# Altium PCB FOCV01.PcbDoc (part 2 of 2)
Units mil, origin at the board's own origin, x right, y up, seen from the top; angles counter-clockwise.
Board outline 3845.03 x 2425.03 mil, 2 copper layers (Top Layer, Bottom Layer); 118 components, 90 nets, 380 pads, 232 vias.
Unrouted connection lines stored in the file: 2.
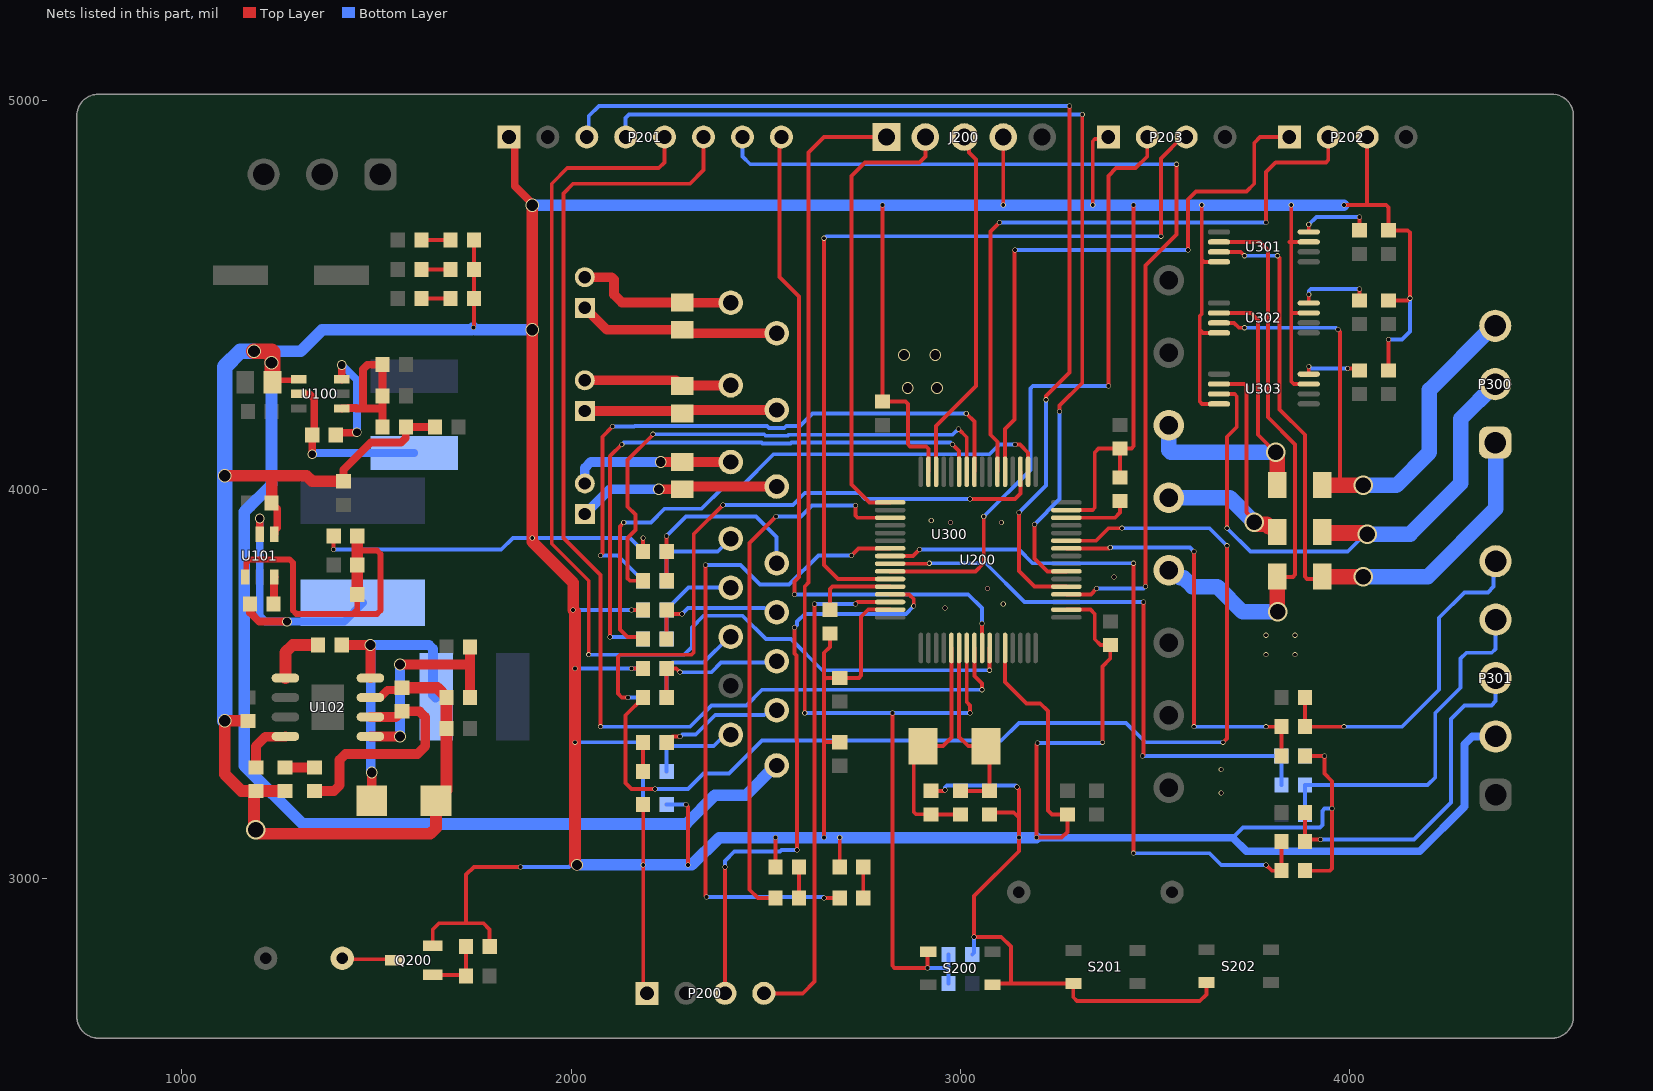
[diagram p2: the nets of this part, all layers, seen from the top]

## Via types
v1: diameter 13, hole 10, Top Layer to Bottom Layer, 174 vias
v2: diameter 30, hole 25, Top Layer to Bottom Layer, 15 vias
v3: diameter 25, hole 20, Top Layer to Bottom Layer, 12 vias
v4: diameter 35, hole 30, Top Layer to Bottom Layer, 11 vias
v5: diameter 24, hole 12, Top Layer to Bottom Layer, 8 vias
v6: diameter 50, hole 40, Top Layer to Bottom Layer, 7 vias
v7: diameter 45, hole 35, Top Layer to Bottom Layer, 4 vias
v8: diameter 20, hole 15, Top Layer to Bottom Layer, 1 vias

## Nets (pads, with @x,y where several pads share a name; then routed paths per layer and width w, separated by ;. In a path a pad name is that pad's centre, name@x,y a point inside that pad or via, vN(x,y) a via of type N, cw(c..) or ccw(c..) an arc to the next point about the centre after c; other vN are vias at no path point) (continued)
DGND: C103.1 C106.1 C107.1 C109.1 C110.2 C111.1 C112.1 C113.1 C200.1 C201.1 C202.1 C203.1 C204.2 C205.1 C206.1 C207.1 C208.1 C209.1 C306.1 C307.1 C308.1 C309.1 C310.1 C311.1 C312.1 C313.1 C314.1 C316.1 C317.1 C318.1 C319.1 C320.1 D100.1 D101.K D102.K D103.K J200.2 P200.1 P201.1 P202.3 P203.1 P301.2 Q200.2 R101.1 R102.2 R104.1 R108.1 R201.2 R205.2 R206.2 R207.2 R308.1 S200.1 S201.2 S202.2 U100.1 U101.1 U102.7 U200.12 U200.18 U200.31 U200.47 U200.63 U300.16 U301.4 U301.7 U302.4 U302.7 U303.4 U303.7 | length 25810.5
  Top Layer w10: v1(1389.68,3845.32) R104.1@1389.68,3880 ; Q200.2@1644.21,2827.4 1644.21,2869.21 1660,2885 1730,2885 ; v1(1748.81,4415.31) 1750.31,4416.81 D102.K@1750.31,4490 D103.K@1750.31,4565 D101.K@1750.32,4640 ; R205.2@1790.63,2825 1790.63,2869.37 1775,2885 1730,2885 ; v1(1870,3030) 1750,3030 1730,3010 1730,2885 ; v1(2155,3540) C311.1@2184.68,3540 ; v1(2155,3690) C309.1@2184.68,3690 ; C313.1@2184.69,3190 2185,3189.69 v1(2185,3035) 2185,2715 P200.1@2195,2705 ; C307.1@2184.68,3840 2184.68,3874.68 v1(2185,3875) ; v1(2295,3190) 2295,3189.19 2300,3184.19 v1(2300,3035) ; R207.2@2524.68,3029.69 2525,3030 v1(2525,3105) ; v1(2650,3105) 2650,3350.32 ; R201.2@2665,3629.68 2665,3595 2650,3580 2650,3509.46 ; C208.1@2680,3515.32 2655.86,3515.32 2650,3509.46 ; R206.2@2689.69,3029.69 2690,3030 v1(2690,3105) ; C207.1@2690,3350.32 2650,3350.32 ; C208.1@2690,3515.31 2739.14,3515.31 2745,3521.17 2745,3672.5 2763.18,3690.68 U200.63@2819.42,3690.68 ; v1(2800,4730) C209.1@2800,4225.31 2859.14,4225.31 2865,4219.46 2865,4115.86 2870.86,4110 2911.98,4110 2917.84,4104.14 U200.47@2917.84,4045 ; C200.1@2925,3225.31 2957.14,3225.31 2959.19,3227.36 v1(2960,3227.36) ; C201.1@3075,3164.68 3080.32,3170 3137.07,3170 3150,3157.07 ; S200.1@3082.68,2727.17 3085.51,2730 3129.14,2730 3129.5,2730.35 ; v1(3110,4730) J200.2@3110,4905 ; U200.12@3114.69,3592.25 3114.69,3505.31 3170,3450 3205,3450 3225,3430 3225,3175 3235.32,3164.68 C202.1@3275,3164.68 3275,3120 3260,3105 v1(3195,3105) 3195,3345 v1(3197.93,3347.93) ; v1(3145,3235) 3145,3234.19 3150,3229.19 3150,3157.07 ; U200.18@3272.16,3690.68 3334.32,3690.68 3345,3680 3345,3620 3345,3614.69 3359.69,3600 C206.1@3384.69,3600 ; U200.31@3272.16,3946.58 3339.14,3946.58 3345,3952.43 3345,4095 3354.68,4104.69 C205.1@3410,4104.69 ; v1(3340,4730) 3340,4894.14 3345.86,4900 3375,4900 P203.1@3380,4905 ; v1(3365,3350) 3365,3545 3385,3565 C206.1@3385,3599.69 ; C204.2@3410,4030.32 C205.1@3410,4104.69 ; v1(3445,4730) 3445,4110.54 3439.14,4104.69 C205.1@3410,4104.69 ; v1(3620,4730) 3620,4590 ; S202.2@3632.32,2732.68 3632.32,2702.32 3615,2685 3300,2685 3290,2695 S201.2@3290,2730.35 3129.5,2730.35 ; U303.4@3664.43,4219.26 3620.86,4219.26 3615,4225.11 3615,4410 ; U302.4@3664.43,4401.76 3623.24,4401.76 3615,4410 ; U301.4@3664.43,4584.26 3625.74,4584.26 3620,4590 ; 3845,4635.44 U301.7@3894.9,4635.44 ; 3850,4723.01 3850,4453.15 ; C320.1@3885.32,3020 3949.14,3020 3955,3025.86 3955,3250 3935,3270 v1(3935,3315) C312.1@3885.32,3315 ; U303.7@3894.9,4270.44 3856.33,4270.44 3850,4276.77 3850,4453.15 ; U302.7@3894.9,4452.94 3850.21,4452.94 3850,4453.15 ; v1(3985,4730) 4045,4730 ; P202.3@4045,4905 4045,4730 ; C318.1@4100,4305.31 v1(4100,4385) ; C317.1@4100,4485.31 4100.31,4485 4149.14,4485 v1(4155,4490.86) 4155,4659.46 4149.14,4665.31 C316.1@4100,4665.31 4100,4724.14 4094.14,4730 4045,4730 ; 2650,3350.32 2650,3509.46 ; 3129.5,2730.35 3129.5,2825.5 3105,2850 v1(3035,2850) 3035,2955 3150,3070 v1(3150,3105) 3150,3157.07 ; 3615,4410 3615,4445 3620,4450 3620,4590
  Top Layer w15: R102.2@1232.54,4275 1237.54,4280 1297.78,4280 U100.1@1300.17,4282.39
  Top Layer w20: C106.1@1230.31,3965 1230.31,3964.02 1245,3949.33 1245,3901.29 1237.39,3893.69 U101.1@1237.39,3884.83 ; C107.1@1415,4020.31 1415,4050 1485,4120 1563.28,4120 1575,4131.72 1575,4159.37 R101.1@1575.63,4160 C103.1@1650,4160 ; U102.7@1484.15,3465 1508.76,3465 1528.21,3484.46 1559.14,3484.46 C111.1@1565,3490.31 ; P201.1@1840,4905 1855,4890 1855,4779.06 1900,4734.06 v4(1900,4730)
  Top Layer w30: v4(1110,4035) 1230.31,4035 ; 1169.68,3225 1152.57,3225 1110,3267.57 v4(1110,3405) 1169.69,3405 C109.1@1170,3404.69 ; v6(1190,3125) v6@1189.64,3125 ; C106.1@1230.31,3965 1230.31,4035 ; C112.1@1265,3224.69 C113.1@1190,3224.69 1185,3219.69 1185,3129.64 v6@1189.64,3125 ; C107.1@1415,4020.31 1334.69,4020.31 1320,4035 1230.31,4035 ; C111.1@1565,3490.31 1649.69,3490.31 1650,3490 1655.67,3490 1679.68,3465.98 R108.1@1679.68,3465 C110.2@1679.69,3385 1679.69,3227.01 D100.1@1652.68,3200 1652.68,3129.64 1638.03,3115 1199.64,3115 v6@1189.64,3125 ; v4(1900,4730) v4(1900,4410) v1(1900,3875) 1900,3865 2005,3760 v1(2005,3690) 2010,3685 v1(2010,3540) v1(2010,3350) 2010,3040 v2(2015,3035)
  Top Layer w40: v4(1185,4355) 1230.09,4355 1232.54,4352.54 R102.2@1232.54,4275
  Bottom Layer w10: v1(1389.68,3845.32) 1820.32,3845.32 1850,3875 v1(1900,3875) 2150.67,3875 2184.69,3840.98 C306.1@2184.69,3840 2185,3840.31 v1(2185,3875) ; v1(1870,3030) 1994.59,3030 1999.59,3035 v2(2015,3035) ; v1(2005,3690) C308.1@2184.68,3690 ; v1(2010,3350) C314.1@2184.69,3350 ; v1(2010,3540) C310.1@2184.68,3540 ; R308.1@2245.31,3190 v1(2295,3190) ; v1(2960,3227.36) 2960.57,3227.93 2960.57,3234.14 2964.96,3238.53 3141.47,3238.53 v1(3145,3235) ; C203.1@3030.31,2805 3035,2809.68 v1(3035,2850) ; v1(3197.93,3347.93) 3362.12,3347.93 3364.19,3350 v1(3365,3350) ; 3700,3105 3726.31,3131.31 3924.14,3131.31 3930,3137.17 3930,3173.57 3935.86,3179.43 3954.43,3179.43 v1(3955,3180) ; C319.1@3885,3315 v1(3935,3315) ; v1(4100,4385) 4135,4385 4155,4405 v1(4155,4490.86)
  Bottom Layer w20: v1(3195,3105) 3700,3105 3735,3070 4180,3070 4295,3185 4295,3345 4315,3365 P301.2@4375,3365
  Bottom Layer w30: v4(1185,4355) 1305,4355 1360,4410 1743.5,4410 v1(1748.81,4415.31) ; v4(1230,4325) 1230,4012.15 1160,3942.15 1160,3290 1310,3140 2295,3140 2369,3214 2449,3214 2525.51,3290.51 U300.16@2527.76,3290.51 ; v1@1748.81,4415 1753.81,4410 v4(1900,4410) ; v4(1900,4730) v1(2800,4730) v1(3110,4730) v1(3445,4730) v1(3620,4730) v1(3850,4730) v1(3985,4730) ; v2(2015,3035) v1(2185,3035) v1(2300,3035) 2310,3035 2380,3105 v1(2525,3105) v1(2650,3105) v1(2690,3105) v1(3150,3105) v1(3195,3105)
  Bottom Layer w40: v4(1110,3405) v4(1110,4035) 1110,4315 1150,4355 v4(1185,4355)
  other v1: 3670,3220 3670,3280 3785,3575 3860,3575 3785,3625 3860,3625 2960,3695 3110,3705 3070,3745 3395,3775 2975,3915 3105,3915 2925,3920
  other v2: 2865,4260 2940,4260 2855,4345 2935,4345
FLASH_LED: D200.A U200.55 | length 1730.6
  Top Layer w10: v1(2345,3805) 2345,2955 v1(2347.5,2952.5) ; v1(2650,2950) 2689.37,2950 D200.A@2689.68,2949.69 ; v1(2720,3830) 2738.16,3848.16 U200.55@2819.42,3848.16
  Bottom Layer w10: v1(2345,3805) 2435,3805 2485,3755 2560,3755 2635,3830 v1(2720,3830) ; v1(2347.5,2952.5) 2647.5,2952.5 v1(2650,2950)
HSE_IN: C200.2 OSC200.1 R200.1 U200.5 | length 613.8
  Top Layer w10: U200.5@2976.89,3592.25 2976.89,3361.89 2955.01,3340.01 OSC200.1@2904.29,3340.01 2880,3315.72 2880,3170.86 2885.86,3165 2924.69,3165 C200.2@2925,3164.69 R200.1@3000,3164.69
HSE_OUT: C201.2 OSC200.2 R200.2 U200.6 | length 501.2
  Top Layer w10: U200.6@2996.58,3592.25 2996.58,3363.42 3020,3340 OSC200.2@3065.71,3340 3075,3330.71 C201.2@3075,3225.32 R200.2@3000,3225.32
I2C1_SCL: P200.3 U200.61 | length 1529.7
  Top Layer w10: P200.3@2395,2705 v1(2395,3030) ; v1(2573.5,3645) 2573.5,3578.24 2578.5,3573.24 2578.5,3357.5 2580,3356 v1(2580,3073.5) ; U200.61@2819.42,3730.05 2868.3,3730.05 2880,3718.35 v1(2880,3700)
  Bottom Layer w10: v1(2395,3030) 2395,3045 2419,3069 2536.22,3069 2540.72,3073.5 v1(2580,3073.5) ; v1(2573.5,3645) 2574.31,3645 2580.17,3650.86 2580.57,3650.86 2580.57,3660.57 2600,3680 2860,3680 v1(2880,3700)
I2C1_SDA: P200.4 U200.62 | length 1309.1
  Top Layer w10: P200.4@2495,2705 2595,2705 2625,2735 v1(2625,3705) ; v1(2730,3705) 2735.01,3710.01 2819.07,3710.01 U200.62@2819.42,3710.36
  Bottom Layer w10: v1(2625,3705) v1(2730,3705)
LCD_BLK: P201.8 U200.9 | length 1801.6
  Top Layer w10: P201.8@2540,4905 2535,4900 2535,4545 2585,4495 2585,3775 2573.5,3763.5 v1(2573.5,3730) ; v1(3055,3655) 3055.63,3654.37 U200.9@3055.63,3592.25
  Bottom Layer w10: v1(2573.5,3730) 3020,3730 3055,3695 v1(3055,3655)
LCD_DC: P201.6 U200.8 | length 3013.7
  Top Layer w10: v1(2075,3390) 2075,3780 1980,3875 1980,4760 2005,4785 2305,4785 2340,4820 P201.6@2340,4905 ; U200.8@3035.95,3592.25 3035.95,3520 3055,3500.95 v1(3055,3485)
  Bottom Layer w10: v1(2075,3390) 2305,3390 2360,3445 2450,3445 2490,3485 v1(3055,3485)
LCD_RES: P201.5 U200.10 | length 2843.4
  Top Layer w10: v1(2045,3575) 2045,3765 1950,3860 1950,4785 1990,4825 2225,4825 2240,4840 P201.5@2240,4905 ; v1(3075,3535) 3075.16,3535.16 3075.16,3592.09 U200.10@3075.32,3592.25
  Bottom Layer w10: v1@2044.85,3575 2290,3575 2310,3595 2310,3645 2340,3675 2440,3675 2500,3615 2565,3615 2645,3535 v1(3075,3535)
NetBuzzer200_2: Buzzer200.2 Q200.3 | length 136
  Top Layer w10: Buzzer200.2@1411.85,2795 1414.35,2792.5 1543.29,2792.5 Q200.3@1545.79,2790
NetC100_1: C100.1 U100.6 | length 284.3
  Top Layer w20: C100.1@1395.31,4140 1400.82,4145.5 1448.46,4145.5 v3(1449.42,4146.46) ; v3@1410,4320 v3(1410.41,4319.59) U100.6@1410.41,4282.4
  Bottom Layer w20: v3(1410.41,4319.59) 1450,4280 1450,4147.05 v3(1449.42,4146.46)
NetC100_2: C100.2 L100.1 U100.2 | length 448.2
  Top Layer w20: U100.2@1300.17,4245 1301,4244.17 1328.28,4244.17 1340,4232.45 C100.2@1340,4142.72 ; C100.2@1334.69,4140 1334.69,4090.31 v3(1335,4090)
  Bottom Layer w20: v3(1335,4090) 1336.35,4090 1339.66,4093.31 L100.1@1596.95,4093.31
NetC102_1: C102.1 R100.1 R101.2 U100.4 | length 423.1
  Top Layer w20: U100.4@1410.42,4207.6 1411.24,4208.43 1427.61,4208.43 1427.99,4208.8 1447.16,4208.8 1448.36,4207.6 1462.6,4207.6 ; R101.2@1515,4160 1515,4210 ; 1462.6,4207.6 1512.6,4207.6 1515,4210 ; 1462.6,4207.6 1465,4210 1465,4308.28 1476.72,4320 C102.1@1515,4320 R100.1@1515,4240 1515,4210
NetC104_1: C104.1 U101.6 | length 70.4
  Top Layer w20: C104.1@1235.31,3705 1236.57,3706.25 1236.57,3773.76 U101.6@1237.39,3774.59
NetC104_2: C104.2 L101.1 U101.2 | length 708.5
  Top Layer w20: C104.2@1174.68,3705 1174.68,3682.66 1175.99,3682.66 1198.65,3660 v3(1270,3660) ; U101.2@1200,3884.83 v3(1200,3925)
  Bottom Layer w20: v3(1200,3925) 1200,3675 1215,3660 v3(1270,3660) 1416.58,3660 L101.1@1465,3708.42
NetC105_1: C105.1 R103.1 R104.2 U101.4 | length 932.1
  Top Layer w15: U101.4@1162.6,3774.59 1165,3776.99 1165,3811.21 1173.79,3820 1276.21,3820 1285,3811.21 1285,3688.79 1293.79,3680 1440,3680 ; C105.1@1450.31,3730 1450.31,3690.31 1440,3680 ; 1450.32,3842.5 1501.21,3842.5 1510,3833.71 1510,3688.79 1501.21,3680 1440,3680
  Top Layer w30: C105.1@1450.31,3730 R103.1@1450.31,3805 1450.32,3842.5 R104.2@1450.32,3880
NetC108_1: C108.1 U102.1 | length 157.6
  Top Layer w30: U102.1@1265.85,3515 1265.85,3580.85 1285,3600 C108.1@1349.69,3600
NetC108_2: C108.2 D100.2 L102.1 U102.8 | length 852.8
  Top Layer w25: C108.2@1410.31,3600 v2(1484.15,3600) U102.8@1484.15,3515 ; D100.2@1487.32,3200 v2(1487.32,3272.32)
  Bottom Layer w25: v2(1487.32,3272.32) 1487.32,3273.68 1485,3276 1485,3599.15 v2(1484.15,3600) 1635,3600 1645,3590 1645,3471.35 L102.1@1651.35,3465
NetC111_2: C111.2 R107.2 U102.6 | length 600.5
  Top Layer w25: R107.2@1340,3224.68 1390.36,3224.68 1405,3239.33 1405,3305 1420,3320 1605.36,3320 1625,3339.64 1625,3415.04 1610.36,3429.69 C111.2@1565,3429.69 1564.02,3429.69 1549.33,3415 U102.6@1484.15,3415 U102.6@1484.84,3414.31
NetC112_2: C112.2 R107.1 | length 75
  Top Layer w25: C112.2@1265,3285.31 R107.1@1340,3285.31
NetC113_2: C113.2 U102.4 | length 140.9
  Top Layer w25: C113.2@1190,3285.31 1190,3340 1214.31,3364.31 1265.16,3364.31 U102.4@1265.85,3365
NetC204_1: C204.1 U200.30 | length 172.9
  Top Layer w10: U200.30@3272.16,3926.9 3367.21,3926.9 3396.9,3926.9 3410,3940 C204.1@3410,3969.68
NetC300_1: C300.1 C301.1 U300.2 | length 525.1
  Top Layer w25: C300.1@2035,4466.26 2091.3,4409.96 C301.1@2285,4409.96 2294.22,4400.74 U300.2@2527.76,4400.74
  Bottom Layer w10: U300.2@2524.07,4404.43 U300.2@2527.76,4400.74
NetC300_2: C300.2 C301.2 U300.1 | length 424.7
  Top Layer w25: C300.2@2035,4545 2104.14,4545 2110,4539.14 2110,4500 2129.96,4480.04 C301.2@2285,4480.04 2285.55,4479.49 U300.1@2409.65,4479.49
NetC302_1: C302.1 C304.1 U300.4 | length 499.1
  Top Layer w25: C302.1@2035,4201.26 2278.7,4201.26 C304.1@2285,4194.96 2293.93,4203.9 U300.4@2527.76,4203.9
NetC302_2: C302.2 C304.2 U300.3 | length 381.6
  Top Layer w25: C302.2@2035,4280 2270.04,4280 C304.2@2285,4265.04 2286.85,4266.89 U300.3@2409.65,4266.89
NetC303_1: C303.1 C305.1 U300.6 | length 522.1
  Top Layer w25: v2(2225,4000) v2(2225,4000) C305.1@2285,3999.96 2292.08,4007.04 U300.6@2527.76,4007.04
  Bottom Layer w25: C303.1@2035,3936.26 2098.74,4000 v2(2225,4000)
NetC303_2: C303.2 C305.2 U300.5 | length 420.9
  Top Layer w25: v2(2230,4070) C305.2@2285,4070.04 C305.2@2285,4070.04 U300.5@2409.65,4070.03
  Bottom Layer w25: C303.2@2035,4015 2035,4055 2050,4070 v2(2230,4070)
NetC306_2: C306.2 R300.2 U300.7 | length 253.1
  Bottom Layer w10: R300.2@2245.32,3765 C306.2@2245.31,3840 2376.46,3840 U300.7@2409.65,3873.18
NetC307_2: C307.2 R301.2 U300.8 | length 507.8
  Top Layer w10: v1(2245,3880) 2245.31,3879.69 C307.2@2245.31,3840 R301.2@2245.32,3765 ; U300.8@2527.56,3810 U300.8@2527.76,3810.19
  Bottom Layer w10: v1(2245,3880) 2295,3930 2475,3930 2527.76,3877.24 U300.8@2527.76,3810.19
NetC308_2: C308.2 R302.2 U300.9 | length 263.6
  Bottom Layer w10: R302.2@2245.32,3615 C308.2@2245.32,3690 2245.32,3690.98 2301.53,3747.2 U300.9@2409.65,3747.2
NetC309_2: C309.2 R303.2 U300.10 | length 372.4
  Top Layer w10: R303.2@2245,3615 2245,3689.69 C309.2@2245.32,3690 2255.32,3680 v1(2285,3680)
  Bottom Layer w10: v1(2285,3680) 2300,3695 2495.4,3695 2496.05,3694.35 2517.62,3694.35 U300.10@2527.76,3684.21
NetC310_2: C310.2 R304.2 U300.11 | length 275.2
  Bottom Layer w10: R304.2@2245.32,3465 C310.2@2245.32,3540.98 ; C310.2@2245.32,3540 C310.2@2245.32,3540.98 ; U300.11@2409.65,3620.5 U300.11@2409.65,3621.22 2406.22,3621.22 2340,3555 2260.32,3555 2259.61,3554.29 2258.62,3554.29 C310.2@2245.32,3540.98
NetC311_2: C311.2 R305.2 U300.12 | length 377.8
  Top Layer w10: R305.2@2245.32,3465 C311.2@2245.32,3540 2270,3540 v1(2280,3530) ; U300.12@2524.53,3555 U300.12@2527.76,3558.22
  Bottom Layer w10: v1(2280,3530) 2360,3530 2385,3555 2524.53,3555 U300.12@2527.76,3558.22
NetC314_2: C314.2 R307.2 U300.15 | length 256.6
  Bottom Layer w10: R307.2@2245.32,3275 C314.2@2245.32,3350.98 ; C314.2@2245.32,3350 2255.32,3340 2366.31,3340 2395.55,3369.25 U300.15@2409.65,3369.25
NetD101_A: D101.A R111.1 | length 74.4
  Top Layer w10: R111.1@1615.31,4640 D101.A@1689.68,4640
NetD102_A: D102.A R112.1 | length 74.4
  Top Layer w10: R112.1@1615.31,4490 D102.A@1689.68,4490
NetD103_A: D103.A R110.1 | length 75.4
  Top Layer w10: R110.1@1615.31,4565 1687.18,4565 D103.A@1689.68,4562.5
NetD200_K: D200.K R206.1 | length 80
  Top Layer w10: D200.K@2750.31,2949.69 R206.1@2750.32,3029.68
NetD201_K: D201.K R207.1 | length 80
  Top Layer w10: D201.K@2585.31,2949.69 R207.1@2585.31,3029.69
NetD300_K: D300.K R306.2 | length 75.8
  Top Layer w10: D300.K@2184.69,3275 2184.69,3348.18 R306.2@2186.5,3350
NetP301_3: P301.3 R315.1 R318.2 | length 899.2
  Top Layer w10: R318.2@3885.32,3170 R315.1@3885.31,3095 3890.31,3100 v1(3925,3100)
  Bottom Layer w10: v1(3925,3100) 4165,3100 4260,3195 4260,3410 4295,3445 4364.14,3445 4375,3455.86 P301.3@4375,3515
NetP301_4: P301.4 R316.1 R319.2 | length 925.2
  Bottom Layer w10: R319.2@3885.32,3165 R316.1@3885.32,3240 4200,3240 4220,3260 4220,3425 4285,3490 4285,3565 4300,3580 4365,3580 4375,3590 P301.4@4375,3665
NetP301_5: P301.5 R317.1 R320.2 | length 884.2
  Top Layer w10: R320.2@3885.32,3465 R317.1@3885.31,3390 v1(3985,3390)
  Bottom Layer w10: v1(3985,3390) 4135,3390 4230,3485 4230,3670 4295,3735 4355,3735 4370,3750 4370,3810 P301.5@4375,3815
NetQ200_1: Q200.1 R204.2 R205.1 | length 161.7
  Top Layer w10: Q200.1@1644.21,2752.6 1727.09,2752.6 R204.2@1729.68,2750 1729.68,2824.68 R205.1@1730,2825
NetR106_1: R106.1 R108.2 U102.5 | length 571.2
  Top Layer w25: U102.5@1484.15,3365 v2(1560,3365) ; v2(1560,3550) 1740.32,3550 ; R108.2@1740.32,3465 1740.32,3550 ; R106.1@1740.31,3595 1740.32,3550
  Bottom Layer w25: v2(1560,3365) v2(1560,3550)
NetR201_1: R201.1 U200.60 | length 209.6
  Top Layer w10: R201.1@2665,3691.13 2665,3743.87 2670.86,3749.73 U200.60@2819.42,3749.73
NetR306_1: R306.1 U300.14 | length 316.5
  Top Layer w10: R306.1@2245.31,3350 2260.31,3365 v1(2280,3365)
  Bottom Layer w10: v1(2280,3365) 2280.81,3365 2285.81,3370 2320,3370 2370,3420 2495.4,3420 2497.5,3422.1 2517.62,3422.1 U300.14@2527.76,3432.24
NetR307_1: R307.1 R308.2 | length 85
  Bottom Layer w10: R308.2@2184.68,3190 2184.68,3225 R307.1@2184.69,3275
NetR312_1: R312.1 U301.8 | length 198.2
  Top Layer w10: U301.8@3894.9,4661.03 v1(3894.9,4679.9) v1@3895,4680 ; R312.1@4020.71,4661.03 R312.1@4025,4665.31 v1(4025,4700)
  Bottom Layer w10: v1(3894.9,4679.9) 3915,4700 v1(4025,4700)
NetR313_1: R313.1 U302.8 | length 202.4
  Top Layer w10: U302.8@3894.9,4478.53 3894.9,4499.9 v1(3895,4500) ; R313.1@4018.21,4478.53 R313.1@4025,4485.31 v1(4025,4515)
  Bottom Layer w10: v1(3895,4500) 3895,4509.14 3900.86,4515 v1(4025,4515)
NetR314_1: R314.1 U303.8 | length 157.2
  Top Layer w10: U303.8@3894.9,4296.03 3894.9,4314.9 v1(3895,4315) ; v1(3995,4310) 4010.31,4310 4015.31,4315 R314.1@4025,4305.31
  Bottom Layer w10: v1(3895,4315) 3900,4310 v1(3995,4310)
NRST: C203.2 J200.5 R203.1 S200.4 U200.7 | length 3210.6
  Top Layer w10: v1(2600,3425) 2600,3750 2610,3760 2610,4865 2650,4905 J200.5@2810,4905 ; v1(2825,3425) 2825,2775.86 2830.86,2770 v1(2915,2770) 2915,2809.5 S200.4@2917.32,2811.82 ; U200.7@3016.26,3592.25 3016.26,3453.74 3025,3445 v1(3025,3425)
  Bottom Layer w10: v1(2600,3425) v1(2825,3425) v1(3025,3425) ; v1(2915,2770) 2969.69,2770 ; R203.1@2969.69,2730 2969.69,2765.05 ; 2969.69,2765.05 C203.2@2969.69,2805 2969.69,2765.05
SPI1_MOSI: P201.4 U200.23 | length 2513.5
  Top Layer w10: v1(3190,3910) 3190,3822.37 3223.28,3789.1 U200.23@3272.16,3789.1 ; v1(3255,4200) 3255,4215 3313.12,4273.12 v1(3313.12,4963.12)
  Bottom Layer w10: P201.4@2140,4905 2140,4953.83 2148.67,4962.5 3312.5,4962.5 v1(3313.12,4963.12) ; v1(3190,3910) 3255,3975 v1(3255,4200)
SPI1_NSS: P201.7 U200.20 | length 2502.5
  Top Layer w10: U200.20@3272.16,3730.05 3335.05,3730.05 v1(3350,3745) ; v1(3475,3750) 3475,4575 3555,4655 v1(3555,4835)
  Bottom Layer w10: P201.7@2440,4905 2440,4855 2460,4835 v1(3555,4835) ; v1(3350,3745) 3470,3745 v1(3475,3750)
SPI1_SCK: P201.3 U200.21 | length 2689.4
  Top Layer w10: v1(3150,3940) 3150,3790 3190.27,3749.73 U200.21@3272.16,3749.73 ; v1(3220,4230) 3220,4240 3280,4300 v1(3280,4985)
  Bottom Layer w10: P201.3@2040,4905 2045,4910 2045,4958.83 2071.17,4985 v1(3280,4985) ; v1(3150,3940) 3220,4010 v1(3220,4230)
SWCLK: J200.4 U200.49 | length 1172
  Top Layer w10: U200.49@2819.42,3966.27 2765.86,3966.27 2760,3972.12 2720,4012.12 2720,4805 2755,4840 2895,4840 2910,4855 J200.4@2910,4905
SWDIO: J200.3 U200.46 | length 909.3
  Top Layer w10: U200.46@2937.52,4045 2937.52,4162.52 3040,4265 3040,4846.88 3021.6,4865.28 3021.6,4876.88 3010.45,4888.04 J200.3@2998.84,4888.04
TIM1_CH1: R300.1 U200.41 | length 1566.9
  Top Layer w10: v1(2075,3830) 2075,3830.81 2080,3835.81 2080,4135 v1(2106.25,4161.25) ; v1(3015,4195) 3035.95,4174.05 U200.41@3035.95,4045
  Bottom Layer w10: v1(2075,3830) 2119.68,3830 R300.1@2184.68,3765 ; v1(2106.25,4161.25) 2162.11,4161.25 2163.86,4163 2502.9,4163 2508.5,4157.4 2547.02,4157.4 2552.62,4163 2588,4163 2620,4195 v1(3015,4195)
TIM1_CH1N: R303.1 U200.34 | length 1528.1
  Top Layer w10: v1(2135,3915) 2135,3914.19 2125,3904.19 2125,3640 2145,3620 2179.37,3620 R303.1@2184.37,3615 ; v1(3140,4115) 3152.63,4115 3173.74,4093.89 U200.34@3173.74,4045
  Bottom Layer w10: v1(2135,3915) 2205,3915 2240,3950 2335,3950 2390,4005 2435,4005 2520,4090 3075,4090 3100,4115 v1(3140,4115)
TIM1_CH2: R301.1 U200.42 | length 1369
  Top Layer w10: R301.1@2184.68,3765 2150.86,3765 2145,3770.86 2145,3875 2165,3895 2165,3935 2145,3955 2145,4075 2210,4140 v1(2210,4141.5) ; v1(2995,4155) 3016.26,4133.74 U200.42@3016.26,4045
  Bottom Layer w10: v1(2210,4141.5) 2496.11,4141.5 2500.21,4137.4 2555.3,4137.4 2557.9,4140 2979.59,4140 2994.59,4155 v1(2995,4155)
TIM1_CH2N: R304.1 U200.35 | length 1617.5
  Top Layer w10: v1(2145.81,3465) 2130,3465 2120,3475 2120,3569.14 2125.86,3575 2309.14,3575 2315,3580.86 2315,3885 v1(2390,3960) ; v1(3025,3975) 3140,3975 3154.06,3989.06 U200.35@3154.06,4045
  Bottom Layer w10: v1(2145.81,3465) R304.1@2184.69,3465 ; v1(2390,3960) 2570,3960 2600,3990 2740,3990 2755,3975 v1(3025,3975)
TIM1_CH3: R302.1 U200.43 | length 1527.3
  Top Layer w10: v1(2100,3620) 2100,4085 v1(2130,4115) ; v1(2980,4115) 2996.58,4098.42 U200.43@2996.58,4045
  Bottom Layer w10: v1(2100,3620) 2179.69,3620 R302.1@2184.69,3615 ; v1(2130,4115) 2130.81,4115 2135.81,4120 2489.33,4120 2491.93,4117.4 2563.58,4117.4 2566.18,4120 2974.19,4120 2979.19,4115 v1(2980,4115)
TIM1_CH3N: R305.1 U200.27 | length 2824.8
  Top Layer w10: R305.1@2184.69,3465 2184.69,3464.02 2140,3419.33 2140,3245 2155,3230 v1(2215,3230) ; U200.27@3272.16,3867.84 3347.84,3867.84 3380,3900 v1(3415,3900) ; v1(3675,3350) 3685,3360 v1(3685,3855)
  Bottom Layer w10: v1(2215,3230) 2300,3230 2340,3270 2405,3270 2490,3355 3105,3355 3150,3400 3425,3400 3475,3350 v1(3675,3350) ; v1(3415,3900) 3640,3900 v1(3685,3855)
TIM3_CH1: C320.2 R315.2 U200.56 | length 2073.5
  Top Layer w10: U200.56@2819.42,3828.47 2878.47,3828.47 v1(2895,3845) ; v1(3445,3065) v1(3445,3810) 3445,3601.78 ; v1(3785,3035) 3800,3020 C320.2@3824.68,3020 R315.2@3824.68,3095
  Bottom Layer w10: v1(2895,3845) 3150.31,3845 3185.31,3810 v1(3445,3810) ; v1(3445,3065) 3640,3065 3670,3035 v1(3785,3035)
TIM3_CH2: C319.2 R316.2 U200.57 | length 1520.1
  Top Layer w10: U200.57@2819.42,3808.79 2917.97,3808.79 2919.19,3810 v1(2920,3810) ; v1(3467.5,3315) 3470,3317.5 v1(3470,3710)
  Bottom Layer w10: v1(2920,3810) 3065,3810 3165,3710 v1(3470,3710) ; v1(3467.5,3315) C319.2@3824.37,3315 ; R316.2@3824.69,3240 C319.2@3824.69,3314.69
TIM3_CH3: C312.2 R317.2 U200.26 | length 1081.4
  Top Layer w10: U200.26@3272.16,3848.16 3382.34,3848.16 3384.19,3850 v1(3385,3850) ; v1(3600,3390) v1(3600,3840) ; v1(3785,3390) R317.2@3824.68,3390 ; C312.2@3824.68,3315 R317.2@3824.68,3389.02
  Bottom Layer w10: v1(3385,3850) 3590,3850 v1(3600,3840) ; v1(3600,3390) v1(3785,3390)
U: P300.3 R309.2 U302.3 | length 1431.7
  Top Layer w10: U302.3@3664.43,4427.35 3703,4427.35 3715.35,4415 v1(3730,4415) ; v1(3970,4410) 3970,4409.19 3975,4404.19 3975,4010.48 3975,4010
  Top Layer w40: R309.2@3930.22,4020.2 R309.2@3930.22,4010.48 3975,4010.48 v6@4034.82,4010.48
  Bottom Layer w10: v1(3730,4415) 3965,4415 v1(3970,4410)
  Bottom Layer w40: v6(4035,4010) 4120,4010 4205,4095 4205,4255 4370,4420 P300.3@4374.02,4420
U_IN: R309.1 U300.22 U302.2 | length 893.9
  Top Layer w10: U302.2@3664.43,4452.94 3747.06,4452.94 3765,4435 3765,4140 v6(3810,4095)
  Top Layer w40: v6(3810,4095) 3810,4092.29 3813.78,4088.51 R309.1@3813.78,4010.48
  Bottom Layer w40: U300.22@3535.63,4164.33 3535,4163.7 3535,4100.86 3540.86,4095 v6(3810,4095)
USART1_RX: P203.3 U200.59 | length 2179
  Top Layer w10: v1(2650,4645) 2650,3805 2685.58,3769.42 U200.59@2819.42,3769.42 ; v1(3515,4650) 3515,4850 3570,4905 P203.3@3580,4905
  Bottom Layer w10: v1(2650,4645) 2650.81,4645 2655.81,4650 v1(3515,4650)
USART1_TX: P203.2 U200.58 | length 1661.2
  Top Layer w10: U200.58@2819.42,3789.1 3039.1,3789.1 3060,3810 v1(3060,3930) ; v1(3380,4265) 3380,4805 3400,4825 3450,4825 3480,4855 P203.2@3480,4905
  Bottom Layer w10: v1(3060,3930) 3180,4050 3180,4259.14 3185.86,4265 v1(3380,4265)
USART6_RX: P202.2 U200.38 | length 1703.8
  Top Layer w10: U200.38@3095,4045 3095,4122.07 3077.07,4140 3077.07,4662.07 v1(3100,4685) ; v1(3785,4685) 3785,4815 3810,4840 3939.14,4840 3945,4845.86 P202.2@3945,4905
  Bottom Layer w10: v1(3100,4685) v1(3785,4685)
USART6_TX: P202.1 U200.37 | length 1543.3
  Top Layer w10: U200.37@3114.69,4045 3114.69,4154.69 3139.17,4179.17 3139.17,4614.17 v1(3140,4615) ; v1(3585,4615) 3585,4745 3605,4765 3735,4765 3755,4785 3755,4890 3770,4905 P202.1@3845,4905
  Bottom Layer w10: v1(3140,4615) v1(3585,4615)
USER_LED: D201.A U200.51 | length 1395.1
  Top Layer w10: D201.A@2524.68,2949.69 2524.37,2950 2479.7,2950 2458.5,2971.2 2458.5,3862.31 v1(2526.19,3930) ; v1(2730,3958.49) 2730,3932.75 2735.86,3926.9 U200.51@2819.42,3926.9
  Bottom Layer w10: v1(2526.19,3930) 2590,3930 2618.49,3958.49 v1(2730,3958.49)
V: P300.2 R310.2 U303.3 | length 1499.9
  Top Layer w10: U303.3@3664.43,4244.85 3664.58,4245 3704.14,4245 3710,4239.14 3710,4160 3685,4135 v1(3685,3900)
  Top Layer w40: R310.2@3930.22,3890.48 3932.97,3887.74 v6@4042.26,3887.74
  Bottom Layer w10: v1(3685,3900) 3745,3840 3995,3840 4040,3885 v6(4045,3885)
  Bottom Layer w40: v6(4045,3885) 4155,3885 4285,4015 4285,4180.98 P300.2@4374.02,4270
V_IN: R310.1 U300.21 U303.2 | length 751
  Top Layer w10: U303.2@3664.43,4270.44 3729.14,4270.44 3735,4264.58 3735,3940.86 3755,3920.86 v6(3755,3915)
  Top Layer w40: v6(3755,3915) 3757.71,3915 3762.71,3910 3786.58,3910 3792.61,3903.97 3810.01,3903.97 3813.78,3900.2 R310.1@3813.78,3890.48
  Bottom Layer w40: U300.21@3535.63,3978.11 3691.89,3978.11 v6(3755,3915)
W: P300.1 R311.2 U301.3 | length 1740.2
  Top Layer w10: U301.3@3664.43,4609.85 3720.15,4609.85 v1(3730,4600) ; v1(3815,4600) 3815,4599.19 3820,4594.19 3820,4205 3885,4140 3885,3775.86 3890.86,3770 3924.74,3770 R311.2@3930.22,3775.48
  Top Layer w40: R311.2@3930.22,3775.48 3930.71,3775 v6@4029.59,3775
  Bottom Layer w10: v1(3730,4600) v1(3815,4600)
  Bottom Layer w40: v6(4035,3775) 4200,3775 4375,3950 4375,4119.02 P300.1@4374.02,4120
W_IN: R311.1 U300.20 U301.2 | length 1459.1
  Top Layer w10: U301.2@3664.43,4635.44 3769.56,4635.44 3790,4615 3790,4185 3860,4115 3860,3780.73 3854.14,3774.88 R311.1@3814.39,3774.88
  Top Layer w40: R311.1@3814.39,3774.88 3814.39,3685.61 v6(3815,3685)
  Bottom Layer w40: U300.20@3535.63,3791.89 3546.11,3791.89 3565.48,3772.52 3573.34,3772.52 3595.86,3750 3660,3750 3725,3685 v6(3815,3685)
pads on no net: P100.3 S200.2 S200.3 S201.1 S201.3 S202.1 S202.3 U100.5 U101.5 U102.3 U102.9 U200.2 U200.3 U200.4 U200.11 U200.17 U200.22 U200.24 U200.25 U200.28 U200.29 U200.33 U200.36 U200.39 U200.40 U200.44 U200.45 U200.50 U300.24 U301.1 U302.1 U303.1
copper on no net:
  other v5: 1355.31,3420.31 1355.31,3420.31 1394.68,3420.31 1394.68,3420.31 1355.31,3459.68 1355.31,3459.68 1394.68,3459.68 1394.68,3459.68

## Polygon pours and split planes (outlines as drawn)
DGND on Top Layer "NONET_L02_P-001" (solid, remove dead copper, pour order 0): 2625,2985 3940,2985 3940,4370 2625,4370
DGND on Bottom Layer "NONET_L02_P-001" (solid, remove dead copper, pour order 1): 2625,4380 2625,2985 3940,2985 3940,4380

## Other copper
Top Layer:
  rectangle net 3V3DD: 3865,4210 3925,4250
  rectangle net 3V3DD: 3865,4575 3925,4615
  rectangle net 3V3DD: 3865,4395 3925,4435
  pour cut-out: 3115,3415 3115,3265 3110,3270 2855,3270 2855,3410 2850,3415
Bottom Layer:
  pour cut-out: 2845,3440 2850,3435 3125,3435 3125,3260 3120,3265 2845,3265

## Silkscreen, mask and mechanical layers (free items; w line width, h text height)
Top Overlay:
  circle w10: c865,4880 r108.27
  circle w10: c865,2725 r108.27
  circle w10: c4445,2725 r108.27
  circle w10: c4445,4880 r108.27
  text "A5" at 2009.96,4960.64 h60
  text "C2" at 2210,4960.64 h60
  text "C0" at 2310,4960.64 h60
  text "C1" at 2510,4960.64 h60
  text "A7" at 2109.96,4960 h60
  text "A4" at 2409.96,4960 h60
  text "24V" at 990,4920 h60 r270
  text "DG" at 4010,4810.64 h60
  text "3V3" at 4110,4810.64 h60
  text "TX" at 3805,4810 h60
  text "RX" at 3905,4810 h60
  text "DG" at 1805,4805.64 h60
  text "SCK" at 2000,4805.64 h60
  text "RES" at 2195,4805.64 h60
  text "NSS" at 2389,4805.64 h60
  text "DG" at 3350,4805.64 h60
  text "3V3" at 3635,4805.64 h60
  text "TX" at 3445,4805 h60
  text "RX" at 3540,4805 h60
  text "调试打印口" at 3415,4760.44 h60
  text "通讯UART6" at 3870.04,4758.38 h60
  text "3V3" at 1895,4755.64 h60
  text "MOSI" at 2091,4755.64 h60
  text "DC" at 2310,4755.64 h60
  text "BLK" at 2495,4755 h60
  text "_" at 1345,4740.69 h60
  text "DG" at 3080,4720.64 h60
  text "3V3" at 3180,4720.64 h60
  text "下载口" at 2840.04,4720.25 h60
  text "+" at 1485,4713.77 h60
  text "LCD" at 2215,4685.64 h60
  text "15V" at 1800,4630.64 h60
  text "W_IN" at 3500,4630.61 h60
  text "电机接口" at 4330.04,4595.66 h60
  text "5V" at 1810,4550.64 h60
  text "3V" at 1810,4480.64 h60
  text "U_IN" at 3510.4,4428.94 h60
  text "U->" at 4220.6,4395.64 h60
  text "磁珠" at 1070.03,4263.5 h40
  text "V->" at 4219.7,4255 h60
  text "V_IN" at 3509.8,4248.94 h60
  text "W->" at 4205,4105 h60
  text "霍尔传感器接口" at 4250.66,3874.96 h60 r270
  text "HU->" at 4110,3790.64 h60
  text "HV->" at 4110,3650 h60
  text "HW->" at 4110,3500 h60
  text "DG" at 4260.64,3405 h60 r270
  text "CH3" at 3605,3370.64 h60
  text "5VDD" at 4260.64,3285 h60 r270
  text "故障指示" at 2285.04,3255.36 h60
  text "CH2" at 3605,3220.64 h60
  text "CH1" at 3605,3070.64 h60
  text "DG" at 1170,3070.43 h40
  text "USER" at 2490,2865.71 h60
  text "FLASH" at 2665,2865.71 h60
  text "功能按钮" at 3365.04,2855.36 h60
  text "C10" at 2515,2820.64 h60
  text "B3" at 2685,2820.64 h60
  text "B8" at 2370,2765.64 h60
  text "B9" at 2475,2765.64 h60
  text "BUTTON1" at 3265,2660.64 h60
  text "BUTTON2" at 3605,2660.64 h60
  text "复位按键" at 2885,2650.44 h60
  text "C11" at 3325,2615.64 h60
  text "C12" at 3665,2615.64 h60
  text "DG" at 2155,2610.64 h60
  text "3V3" at 2255,2610.64 h60
  text "SCL" at 2360,2610.64 h60
  text "SDA" at 2480,2610.64 h60
Mechanical 1:
  circle w10: c865,4880 r62.99
  circle w10: c865,2725 r62.99
  circle w10: c4445,2725 r62.99
  circle w10: c4445,4880 r62.99
  lines w10: 735,2640 735,4960 cw(c785,4960) 785,5010 4520,5010 cw(c4520,4960) 4570,4960 4570,2645 cw(c4520,2645) 4520,2595 ; 735,2645 ccw(c785,2645) 785,2595 ; 780,2595 4525,2595
Mechanical 13:
  lines w10: 970,5010 1000,5010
